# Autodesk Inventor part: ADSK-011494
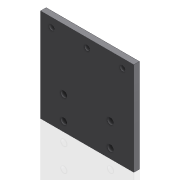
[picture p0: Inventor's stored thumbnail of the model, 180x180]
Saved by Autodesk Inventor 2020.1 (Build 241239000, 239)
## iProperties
Created: 2000-02
Part Number: ADSK-011494
Material: Aluminum
Description: PLT-07,FH,CP,02,040,040,3333333,PLATE,MNT
Document SubType Name: Modeling
Designer: sspink
Density: 2.71 g/cm^3
Appearance: Métal - Acier
Mass: 159.216 g
Surface Area: 227.924 cm^2
Volume: 58.7513 cm^3
Control State: 0
Checked Out: False
Master: False
Shininess: 0.0
Length Units: 11269
Angle Units: 11279
Time Units: 11290
Mass Units: 11283
Length Display Precision: 3
Angle Display Precision: 2
Compacted: True
Cutlength: 4
Material Desc: FLAT,HRS,0.250 X 4.00
Material_number: A084338
Dimensions: 100x100x6 mm
Mass: 0,159 kg
Density: 0.0
Volumn: 0.0
Area: 0.0
PropertySet Name: Model Information
Author: sspink
Revision Number: -
Title: PLT-07,FH,CP,02,040,040,3333333,PLATE,MNT
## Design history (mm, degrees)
node "Solide1"
  node "Extrusion1" dims "d2" = 6, "d3" = 0
  node "Hole1" dims "d9" = 6.6, "d10" = 9.525, "d11" = 6.35, "d12" = 60 deg, "d13" = 19.05, "d14" = 118 deg, "d27" = 6
  node "Hole2" dims "d18" = 5.5, "d19" = 9.525, "d20" = 6.35, "d21" = 60 deg, "d22" = 19.05, "d23" = 118 deg, "d28" = 6
sketch "Sketch1"
  geometry: L1 (-50, -50)-(50, -50); L2 (50, -50)-(50, 50); L3 (50, 50)-(-50, 50); L4 (-50, 50)-(-50, -50); 3 further points
  constraints: 8 end point, 2 midpoint, 2 parallel, 1 horizontal, 1 horizontal alignment, 1 perpendicular, 1 vertical alignment
  dimensions: "d0" = 100 distance between parallel lines of L1 L3; "d1" = 100 distance between parallel lines of L2 L4 (= d0)
sketch "Sketch2"
  geometry: L1 (50, -50)-(-50, -50) reference; L2 (-50, 50)-(50, 50) reference; L3 (-25, -15)-(25, -15); L4 (25, -15)-(25, -40); L5 (25, -40)-(-25, -40); L6 (-25, -40)-(-25, -15); 4 further points
  constraints: 8 end point, 3 vertical alignment, 2 horizontal alignment, 2 midpoint, 2 parallel, 1 horizontal, 1 perpendicular
  dimensions: "d5" = 25 distance of L3.start point (-25, -40); "d7" = 50 distance of point (25, -15) L3.start; "d24" = 10 distance between parallel lines of L1 L5
sketch "Sketch3"
  geometry: L1 (50, -50)-(-50, -50) reference; L2 (-50, 50)-(50, 50) reference; L3 (0, 50)-(0, -50); L4 (-38, 40.5)-(38, 40.5); 1 further point
  constraints: 4 end point, 3 midpoint, 1 horizontal, 1 point on line
  dimensions: "d25" = 76 distance of L4.start L4.end; "d26" = 9.5 distance between parallel lines of L2 L4
node "Corps solides"
node "Corps surfaciques"
